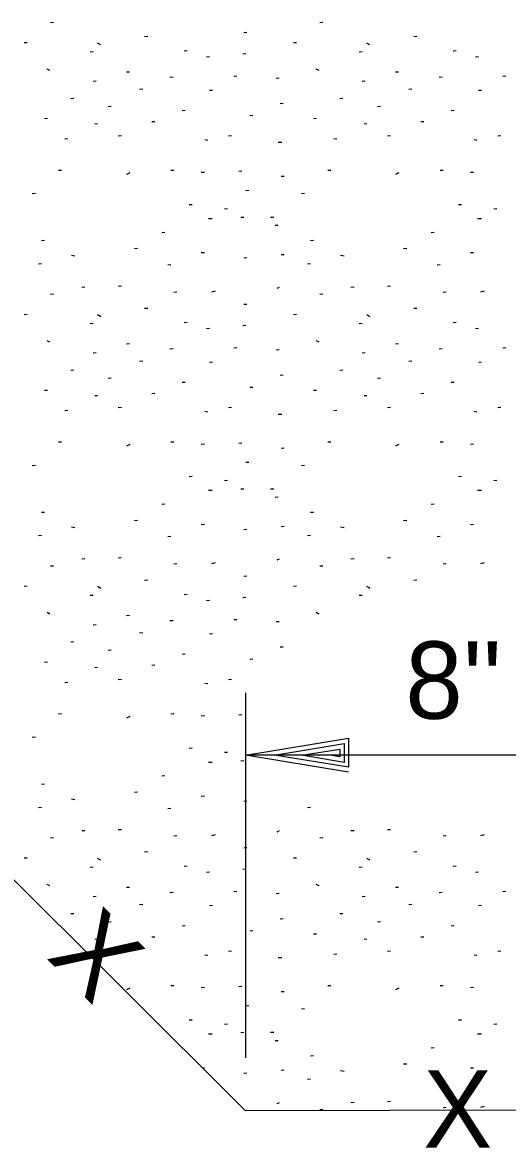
# Model space of a CAD drawing. Extents: x 0 to 320, y -4 to 473.
# Drawn here: x 22.043 to 22.923, y 13.778 to 15.816 of the extents above; entities that cross this region are included whole.
import ezdxf

# ---------------------------------------------------------------- set-up
doc = ezdxf.new("R2010")
doc.units = 0
for name, color, linetype in [('Level 3', 7, 'Continuous'), ('Level 44', 7, 'Continuous'), ('Level 50', 7, 'Continuous')]:
    doc.layers.add(name, color=color, linetype=linetype)

msp = doc.modelspace()

# ---------------------------------------------------------------- linework, layer by layer
at = {"layer": 'Level 3'}
for p, q in [((22.4474, 13.8444), (20.4869, 15.7986)), ((22.0994, 15.8163), (22.0939, 15.8159)), ((22.4501, 15.7981), (22.4446, 15.7976)), ((22.5876, 15.8163), (22.5821, 15.8159)), ((22.0518, 15.7797), (22.0463, 15.7792)), ((22.1849, 15.7757), (22.1793, 15.7791)), ((22.2702, 15.7907), (22.2646, 15.7903)), ((22.5399, 15.7797), (22.5344, 15.7792)), ((22.6731, 15.7757), (22.6674, 15.7791)), ((22.7583, 15.7907), (22.7527, 15.7903)), ((22.1711, 15.7632), (22.1656, 15.7627)), ((22.3417, 15.7649), (22.3362, 15.7644)), ((22.4481, 15.7594), (22.4426, 15.7589)), ((22.6592, 15.7632), (22.6537, 15.7627)), ((22.8298, 15.7649), (22.8243, 15.7644)), ((22.3821, 15.7541), (22.3766, 15.7536)), ((22.8702, 15.7541), (22.8647, 15.7536)), ((22.0929, 15.7293), (22.0877, 15.7318)), ((22.2372, 15.7264), (22.2317, 15.7261)), ((22.3161, 15.7172), (22.3106, 15.7168)), ((22.4316, 15.7192), (22.4261, 15.7187)), ((22.5087, 15.7154), (22.5031, 15.7149)), ((22.5811, 15.7293), (22.5758, 15.7318)), ((22.7253, 15.7264), (22.7198, 15.7261)), ((22.8042, 15.7172), (22.7987, 15.7168)), ((22.9197, 15.7192), (22.9142, 15.7187)), ((22.1766, 15.7099), (22.1711, 15.7094)), ((22.2611, 15.6953), (22.2556, 15.6948)), ((22.6647, 15.7099), (22.6592, 15.7094)), ((22.7492, 15.6953), (22.7437, 15.6948)), ((22.1362, 15.6788), (22.1307, 15.6783)), ((22.3876, 15.6934), (22.3821, 15.6929)), ((22.6243, 15.6788), (22.6188, 15.6783)), ((22.8757, 15.6934), (22.8702, 15.6929)), ((22.2041, 15.6641), (22.1986, 15.6636)), ((22.3381, 15.6567), (22.3326, 15.6563)), ((22.5161, 15.6696), (22.5106, 15.6691)), ((22.6922, 15.6641), (22.6867, 15.6636)), ((22.8262, 15.6567), (22.8207, 15.6563)), ((22.0884, 15.6421), (22.0829, 15.6417)), ((22.2831, 15.6366), (22.2776, 15.6362)), ((22.4609, 15.6476), (22.4554, 15.6472)), ((22.5766, 15.6421), (22.5711, 15.6417)), ((22.7712, 15.6366), (22.7657, 15.6362)), ((22.1793, 15.6321), (22.1744, 15.6326)), ((22.6674, 15.6321), (22.6626, 15.6326)), ((22.1252, 15.6054), (22.1196, 15.6049)), ((22.2224, 15.6109), (22.2169, 15.6104)), ((22.3792, 15.6028), (22.3741, 15.6037)), ((22.4224, 15.6109), (22.4169, 15.6104)), ((22.5136, 15.5987), (22.5068, 15.5987)), ((22.6133, 15.6054), (22.6077, 15.6049)), ((22.7106, 15.6109), (22.7051, 15.6104)), ((22.8673, 15.6028), (22.8622, 15.6037)), ((22.9106, 15.6109), (22.9051, 15.6104)), ((22.1141, 15.5484), (22.1086, 15.5481)), ((22.2376, 15.5439), (22.2317, 15.5409)), ((22.3178, 15.5484), (22.3123, 15.5481)), ((22.3729, 15.5448), (22.3674, 15.5443)), ((22.4408, 15.5467), (22.4353, 15.5462)), ((22.5178, 15.5374), (22.5123, 15.5371)), ((22.6022, 15.5484), (22.5967, 15.5481)), ((22.7257, 15.5439), (22.7198, 15.5409)), ((22.8059, 15.5484), (22.8004, 15.5481)), ((22.8611, 15.5448), (22.8556, 15.5443)), ((22.4536, 15.5118), (22.4481, 15.5113)), ((22.0664, 15.5063), (22.0609, 15.5058)), ((22.5546, 15.5063), (22.5491, 15.5058)), ((22.3509, 15.4862), (22.3454, 15.4857)), ((22.4152, 15.4787), (22.4097, 15.4783)), ((22.8391, 15.4862), (22.8336, 15.4857)), ((22.9033, 15.4787), (22.8978, 15.4783)), ((22.3872, 15.4606), (22.3804, 15.4606)), ((22.4446, 15.4633), (22.4389, 15.4629)), ((22.4991, 15.4633), (22.4928, 15.4633)), ((22.8753, 15.4606), (22.8686, 15.4606)), ((22.3014, 15.4359), (22.2959, 15.4354)), ((22.5068, 15.4487), (22.5013, 15.4483)), ((22.7896, 15.4359), (22.7841, 15.4354)), ((22.0829, 15.4212), (22.0774, 15.4207)), ((22.5711, 15.4212), (22.5656, 15.4207)), ((22.1383, 15.3931), (22.1318, 15.3941)), ((22.2518, 15.4066), (22.2463, 15.4061)), ((22.3729, 15.3992), (22.3674, 15.3988)), ((22.4501, 15.3901), (22.4446, 15.3896)), ((22.5178, 15.3956), (22.5123, 15.3951)), ((22.6264, 15.3931), (22.6199, 15.3941)), ((22.7399, 15.4066), (22.7344, 15.4061)), ((22.8611, 15.3992), (22.8556, 15.3988)), ((22.0774, 15.3789), (22.0719, 15.3786)), ((22.3123, 15.3772), (22.3068, 15.3767)), ((22.5656, 15.3789), (22.5601, 15.3786)), ((22.8004, 15.3772), (22.7949, 15.3767)), ((22.1563, 15.3368), (22.1508, 15.3363)), ((22.2224, 15.3386), (22.2169, 15.3382)), ((22.3233, 15.3277), (22.3178, 15.3272)), ((22.3926, 15.3296), (22.3858, 15.3277)), ((22.5089, 15.3363), (22.5042, 15.3344)), ((22.6444, 15.3368), (22.6389, 15.3363)), ((22.7106, 15.3386), (22.7051, 15.3382)), ((22.8114, 15.3277), (22.8059, 15.3272)), ((22.8807, 15.3296), (22.8739, 15.3277)), ((22.0994, 15.3239), (22.0939, 15.3236)), ((22.5876, 15.3239), (22.5821, 15.3236)), ((22.0518, 15.2873), (22.0463, 15.2868)), ((22.1849, 15.2833), (22.1793, 15.2867)), ((22.2702, 15.2983), (22.2646, 15.2979)), ((22.4501, 15.3057), (22.4446, 15.3052)), ((22.5399, 15.2873), (22.5344, 15.2868)), ((22.6731, 15.2833), (22.6674, 15.2867)), ((22.7583, 15.2983), (22.7527, 15.2979)), ((22.1711, 15.2708), (22.1656, 15.2703)), ((22.3417, 15.2726), (22.3362, 15.2721)), ((22.4481, 15.2671), (22.4426, 15.2666)), ((22.6592, 15.2708), (22.6537, 15.2703)), ((22.8298, 15.2726), (22.8243, 15.2721)), ((22.3821, 15.2617), (22.3766, 15.2612)), ((22.8702, 15.2617), (22.8647, 15.2612)), ((22.0929, 15.2369), (22.0877, 15.2394)), ((22.2372, 15.2341), (22.2317, 15.2337)), ((22.4316, 15.2268), (22.4261, 15.2263)), ((22.5811, 15.2369), (22.5758, 15.2394)), ((22.7253, 15.2341), (22.7198, 15.2337)), ((22.9197, 15.2268), (22.9142, 15.2263)), ((22.1766, 15.2176), (22.1711, 15.2171)), ((22.3161, 15.2248), (22.3106, 15.2244)), ((22.5087, 15.2231), (22.5031, 15.2226)), ((22.6647, 15.2176), (22.6592, 15.2171)), ((22.8042, 15.2248), (22.7987, 15.2244)), ((22.1362, 15.1864), (22.1307, 15.1859)), ((22.2611, 15.2029), (22.2556, 15.2024)), ((22.3876, 15.2011), (22.3821, 15.2006)), ((22.6243, 15.1864), (22.6188, 15.1859)), ((22.7492, 15.2029), (22.7437, 15.2024)), ((22.8757, 15.2011), (22.8702, 15.2006)), ((22.2041, 15.1717), (22.1986, 15.1712)), ((22.3381, 15.1643), (22.3326, 15.1639)), ((22.5161, 15.1772), (22.5106, 15.1767)), ((22.6922, 15.1717), (22.6867, 15.1712)), ((22.8262, 15.1643), (22.8207, 15.1639)), ((22.0884, 15.1497), (22.0829, 15.1493)), ((22.2831, 15.1442), (22.2776, 15.1438)), ((22.4609, 15.1552), (22.4554, 15.1548)), ((22.5766, 15.1497), (22.5711, 15.1493)), ((22.7712, 15.1442), (22.7657, 15.1438)), ((22.1793, 15.1397), (22.1744, 15.1402)), ((22.6674, 15.1397), (22.6626, 15.1402)), ((22.1252, 15.1131), (22.1196, 15.1126)), ((22.2224, 15.1186), (22.2169, 15.1181)), ((22.3792, 15.1104), (22.3741, 15.1113)), ((22.4224, 15.1186), (22.4169, 15.1181)), ((22.5136, 15.1063), (22.5068, 15.1063)), ((22.6133, 15.1131), (22.6077, 15.1126)), ((22.7106, 15.1186), (22.7051, 15.1181)), ((22.8673, 15.1104), (22.8622, 15.1113)), ((22.9106, 15.1186), (22.9051, 15.1181)), ((22.1141, 15.0561), (22.1086, 15.0557)), ((22.2376, 15.0516), (22.2317, 15.0486)), ((22.3178, 15.0561), (22.3123, 15.0557)), ((22.3729, 15.0524), (22.3674, 15.0519)), ((22.4408, 15.0543), (22.4353, 15.0538)), ((22.5178, 15.0451), (22.5123, 15.0447)), ((22.6022, 15.0561), (22.5967, 15.0557)), ((22.7257, 15.0516), (22.7198, 15.0486)), ((22.8059, 15.0561), (22.8004, 15.0557)), ((22.8611, 15.0524), (22.8556, 15.0519)), ((22.0664, 15.0139), (22.0609, 15.0134)), ((22.4536, 15.0194), (22.4481, 15.0189)), ((22.5546, 15.0139), (22.5491, 15.0134)), ((22.3509, 14.9938), (22.3454, 14.9933)), ((22.4152, 14.9863), (22.4097, 14.9859)), ((22.8391, 14.9938), (22.8336, 14.9933)), ((22.9033, 14.9863), (22.8978, 14.9859)), ((22.3872, 14.9682), (22.3804, 14.9682)), ((22.4446, 14.9709), (22.4389, 14.9706)), ((22.4991, 14.9709), (22.4928, 14.9709)), ((22.8753, 14.9682), (22.8686, 14.9682)), ((22.3014, 14.9436), (22.2959, 14.9431)), ((22.5068, 14.9563), (22.5013, 14.9559)), ((22.7896, 14.9436), (22.7841, 14.9431)), ((22.0829, 14.9288), (22.0774, 14.9283)), ((22.5711, 14.9288), (22.5656, 14.9283)), ((22.1383, 14.9007), (22.1318, 14.9017)), ((22.2518, 14.9142), (22.2463, 14.9137)), ((22.3729, 14.9068), (22.3674, 14.9064)), ((22.5178, 14.9032), (22.5123, 14.9027)), ((22.6264, 14.9007), (22.6199, 14.9017)), ((22.7399, 14.9142), (22.7344, 14.9137)), ((22.8611, 14.9068), (22.8556, 14.9064)), ((22.0774, 14.8866), (22.0719, 14.8862)), ((22.3123, 14.8848), (22.3068, 14.8843)), ((22.4501, 14.8977), (22.4446, 14.8972)), ((22.5656, 14.8866), (22.5601, 14.8862)), ((22.8004, 14.8848), (22.7949, 14.8843)), ((22.1563, 14.8444), (22.1508, 14.8439)), ((22.2224, 14.8462), (22.2169, 14.8458)), ((22.5089, 14.8439), (22.5042, 14.8421)), ((22.6444, 14.8444), (22.6389, 14.8439)), ((22.7106, 14.8462), (22.7051, 14.8458)), ((22.0994, 14.8316), (22.0939, 14.8312)), ((22.3233, 14.8353), (22.3178, 14.8348)), ((22.3926, 14.8372), (22.3858, 14.8353)), ((22.5876, 14.8316), (22.5821, 14.8312)), ((22.8114, 14.8353), (22.8059, 14.8348)), ((22.8807, 14.8372), (22.8739, 14.8353)), ((22.2702, 14.8059), (22.2646, 14.8056)), ((22.4501, 14.8133), (22.4446, 14.8128)), ((22.7583, 14.8059), (22.7527, 14.8056)), ((22.0518, 14.7949), (22.0463, 14.7944)), ((22.1711, 14.7784), (22.1656, 14.7779)), ((22.1849, 14.7909), (22.1793, 14.7943)), ((22.3417, 14.7802), (22.3362, 14.7797)), ((22.5399, 14.7949), (22.5344, 14.7944)), ((22.6592, 14.7784), (22.6537, 14.7779)), ((22.6731, 14.7909), (22.6674, 14.7943)), ((22.3821, 14.7693), (22.3766, 14.7688)), ((22.4481, 14.7747), (22.4426, 14.7742)), ((22.0929, 14.7446), (22.0877, 14.7471)), ((22.2372, 14.7417), (22.2317, 14.7413)), ((22.5811, 14.7446), (22.5758, 14.7471)), ((22.1766, 14.7252), (22.1711, 14.7247)), ((22.3161, 14.7324), (22.3106, 14.7321)), ((22.4316, 14.7344), (22.4261, 14.7339)), ((22.5087, 14.7307), (22.5031, 14.7302)), ((22.2611, 14.7106), (22.2556, 14.7101)), ((22.3876, 14.7087), (22.3821, 14.7082)), ((22.1362, 14.6941), (22.1307, 14.6936)), ((22.2041, 14.6793), (22.1986, 14.6788)), ((22.5161, 14.6848), (22.5106, 14.6843)), ((22.0884, 14.6573), (22.0829, 14.6569)), ((22.3381, 14.6719), (22.3326, 14.6716)), ((22.4609, 14.6628), (22.4554, 14.6624)), ((22.1793, 14.6473), (22.1744, 14.6478)), ((22.2831, 14.6518), (22.2776, 14.6514)), ((22.1252, 14.6207), (22.1196, 14.6202)), ((22.2224, 14.6262), (22.2169, 14.6257)), ((22.3792, 14.6181), (22.3741, 14.6189)), ((22.4224, 14.6262), (22.4169, 14.6257)), ((22.4474, 14.6018), (22.4474, 13.9408)), ((22.1141, 14.5637), (22.1086, 14.5633)), ((22.2376, 14.5592), (22.2317, 14.5562)), ((22.3178, 14.5637), (22.3123, 14.5633)), ((22.3729, 14.5601), (22.3674, 14.5596)), ((22.4408, 14.5619), (22.4353, 14.5614)), ((22.0664, 14.5216), (22.0609, 14.5211)), ((22.3509, 14.5014), (22.3454, 14.5009)), ((22.4152, 14.4939), (22.4097, 14.4936)), ((22.3872, 14.4758), (22.3804, 14.4758)), ((22.4446, 14.4786), (22.4389, 14.4782)), ((23.1141, 14.4889), (22.4474, 14.4889)), ((22.3014, 14.4512), (22.2959, 14.4507)), ((22.0829, 14.4364), (22.0774, 14.4359)), ((22.2518, 14.4218), (22.2463, 14.4213)), ((22.3729, 14.4144), (22.3674, 14.4141)), ((22.0774, 14.3942), (22.0719, 14.3938)), ((22.1383, 14.4083), (22.1318, 14.4093)), ((22.3123, 14.3924), (22.3068, 14.3919)), ((22.4501, 14.4053), (22.4446, 14.4048)), ((22.5656, 14.3942), (22.5601, 14.3938)), ((22.1563, 14.3521), (22.1508, 14.3516)), ((22.2224, 14.3538), (22.2169, 14.3534)), ((22.5089, 14.3516), (22.5042, 14.3497)), ((22.6444, 14.3521), (22.6389, 14.3516)), ((22.7106, 14.3538), (22.7051, 14.3534)), ((22.0994, 14.3392), (22.0939, 14.3388)), ((22.3233, 14.3429), (22.3178, 14.3424)), ((22.3926, 14.3448), (22.3858, 14.3429)), ((22.5876, 14.3392), (22.5821, 14.3388)), ((22.8114, 14.3429), (22.8059, 14.3424)), ((22.8807, 14.3448), (22.8739, 14.3429)), ((22.2702, 14.3136), (22.2646, 14.3132)), ((22.4501, 14.3209), (22.4446, 14.3204)), ((22.7583, 14.3136), (22.7527, 14.3132)), ((22.0518, 14.3026), (22.0463, 14.3021)), ((22.1849, 14.2986), (22.1793, 14.3019)), ((22.3417, 14.2878), (22.3362, 14.2873)), ((22.5399, 14.3026), (22.5344, 14.3021)), ((22.6731, 14.2986), (22.6674, 14.3019)), ((22.8298, 14.2878), (22.8243, 14.2873)), ((22.1711, 14.2861), (22.1656, 14.2856)), ((22.3821, 14.2769), (22.3766, 14.2764)), ((22.4481, 14.2823), (22.4426, 14.2818)), ((22.6592, 14.2861), (22.6537, 14.2856)), ((22.8702, 14.2769), (22.8647, 14.2764)), ((22.0929, 14.2522), (22.0877, 14.2547)), ((22.2372, 14.2493), (22.2317, 14.2489)), ((22.5811, 14.2522), (22.5758, 14.2547)), ((22.7253, 14.2493), (22.7198, 14.2489)), ((22.1766, 14.2328), (22.1711, 14.2323)), ((22.3161, 14.2401), (22.3106, 14.2397)), ((22.4316, 14.2421), (22.4261, 14.2416)), ((22.5087, 14.2383), (22.5031, 14.2378)), ((22.6647, 14.2328), (22.6592, 14.2323)), ((22.8042, 14.2401), (22.7987, 14.2397)), ((22.9197, 14.2421), (22.9142, 14.2416)), ((22.2611, 14.2182), (22.2556, 14.2177)), ((22.3876, 14.2163), (22.3821, 14.2158)), ((22.7492, 14.2182), (22.7437, 14.2177)), ((22.8757, 14.2163), (22.8702, 14.2158)), ((22.1362, 14.2017), (22.1307, 14.2012)), ((22.2041, 14.1869), (22.1986, 14.1864)), ((22.5161, 14.1924), (22.5106, 14.1919)), ((22.6243, 14.2017), (22.6188, 14.2012)), ((22.6922, 14.1869), (22.6867, 14.1864)), ((22.3381, 14.1796), (22.3326, 14.1792)), ((22.4609, 14.1704), (22.4554, 14.1701)), ((22.8262, 14.1796), (22.8207, 14.1792)), ((22.1793, 14.1549), (22.1744, 14.1554)), ((22.2831, 14.1594), (22.2776, 14.1591)), ((22.5766, 14.1649), (22.5711, 14.1646)), ((22.6674, 14.1549), (22.6626, 14.1554)), ((22.7712, 14.1594), (22.7657, 14.1591)), ((22.2224, 14.1338), (22.2169, 14.1333)), ((22.3792, 14.1257), (22.3741, 14.1266)), ((22.4224, 14.1338), (22.4169, 14.1333)), ((22.6133, 14.1283), (22.6077, 14.1278)), ((22.7106, 14.1338), (22.7051, 14.1333)), ((22.8673, 14.1257), (22.8622, 14.1266)), ((22.9106, 14.1338), (22.9051, 14.1333)), ((22.5136, 14.1216), (22.5068, 14.1216)), ((22.2376, 14.0668), (22.2317, 14.0638)), ((22.3178, 14.0713), (22.3123, 14.0709)), ((22.3729, 14.0677), (22.3674, 14.0672)), ((22.4408, 14.0696), (22.4353, 14.0691)), ((22.6022, 14.0713), (22.5967, 14.0709)), ((22.7257, 14.0668), (22.7198, 14.0638)), ((22.8059, 14.0713), (22.8004, 14.0709)), ((22.8611, 14.0677), (22.8556, 14.0672)), ((22.5178, 14.0603), (22.5123, 14.0599)), ((22.4536, 14.0347), (22.4481, 14.0342)), ((22.5546, 14.0292), (22.5491, 14.0287)), ((22.3509, 14.0091), (22.3454, 14.0086)), ((22.8391, 14.0091), (22.8336, 14.0086)), ((22.3872, 13.9834), (22.3804, 13.9834)), ((22.4152, 14.0016), (22.4097, 14.0012)), ((22.4446, 13.9862), (22.4389, 13.9858)), ((22.4991, 13.9862), (22.4928, 13.9862)), ((22.8753, 13.9834), (22.8686, 13.9834)), ((22.9033, 14.0016), (22.8978, 14.0012)), ((22.5068, 13.9716), (22.5013, 13.9712)), ((22.5711, 13.9441), (22.5656, 13.9436)), ((22.7896, 13.9588), (22.7841, 13.9583)), ((22.3729, 13.9221), (22.3698, 13.9218)), ((22.7399, 13.9294), (22.7344, 13.9289)), ((22.8611, 13.9221), (22.8556, 13.9217)), ((22.4501, 13.9129), (22.4446, 13.9124)), ((22.5178, 13.9184), (22.5123, 13.9179)), ((22.5656, 13.9018), (22.5601, 13.9014)), ((22.6264, 13.9159), (22.6199, 13.9169)), ((22.8004, 13.9001), (22.7949, 13.8996)), ((22.6444, 13.8597), (22.6389, 13.8592)), ((22.7106, 13.8614), (22.7051, 13.8611)), ((23.0608, 13.8463), (22.4474, 13.8444)), ((22.5089, 13.8592), (22.5042, 13.8573)), ((22.5876, 13.8468), (22.5821, 13.8464)), ((22.8114, 13.8506), (22.8059, 13.8501)), ((22.8807, 13.8524), (22.8739, 13.8506))]:
    msp.add_line(p, q, dxfattribs=at)
at = {"layer": 'Level 50'}
for p, q in [((22.4474, 14.4889), (22.4474, 14.4889)), ((22.4994, 14.4889), (22.4994, 14.4889))]:
    msp.add_line(p, q, dxfattribs=at)
msp.add_lwpolyline([(22.6344, 14.4579), (22.4474, 14.4889), (22.6344, 14.5199), (22.6344, 14.4669), (22.4994, 14.4889), (22.6264, 14.5099), (22.6264, 14.4759), (22.5494, 14.4889), (22.6184, 14.4999), (22.6184, 14.4859), (22.6014, 14.4889)], dxfattribs=at)

# ---------------------------------------------------------------- texts
at = {"layer": 'Level 3'}
msp.add_text("8''", height=0.14, dxfattribs=at).set_placement((22.7374, 14.5549))
at = {"layer": 'Level 44'}
msp.add_text('X', height=0.14, rotation=315, dxfattribs=at).set_placement((22.0845, 14.1221))
msp.add_text('X', height=0.14, dxfattribs=at).set_placement((22.7701, 13.7781))

doc.saveas('drawing.dxf')
